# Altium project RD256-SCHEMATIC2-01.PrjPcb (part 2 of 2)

## Sheet 8.SchDoc
size 420 x 297 mm
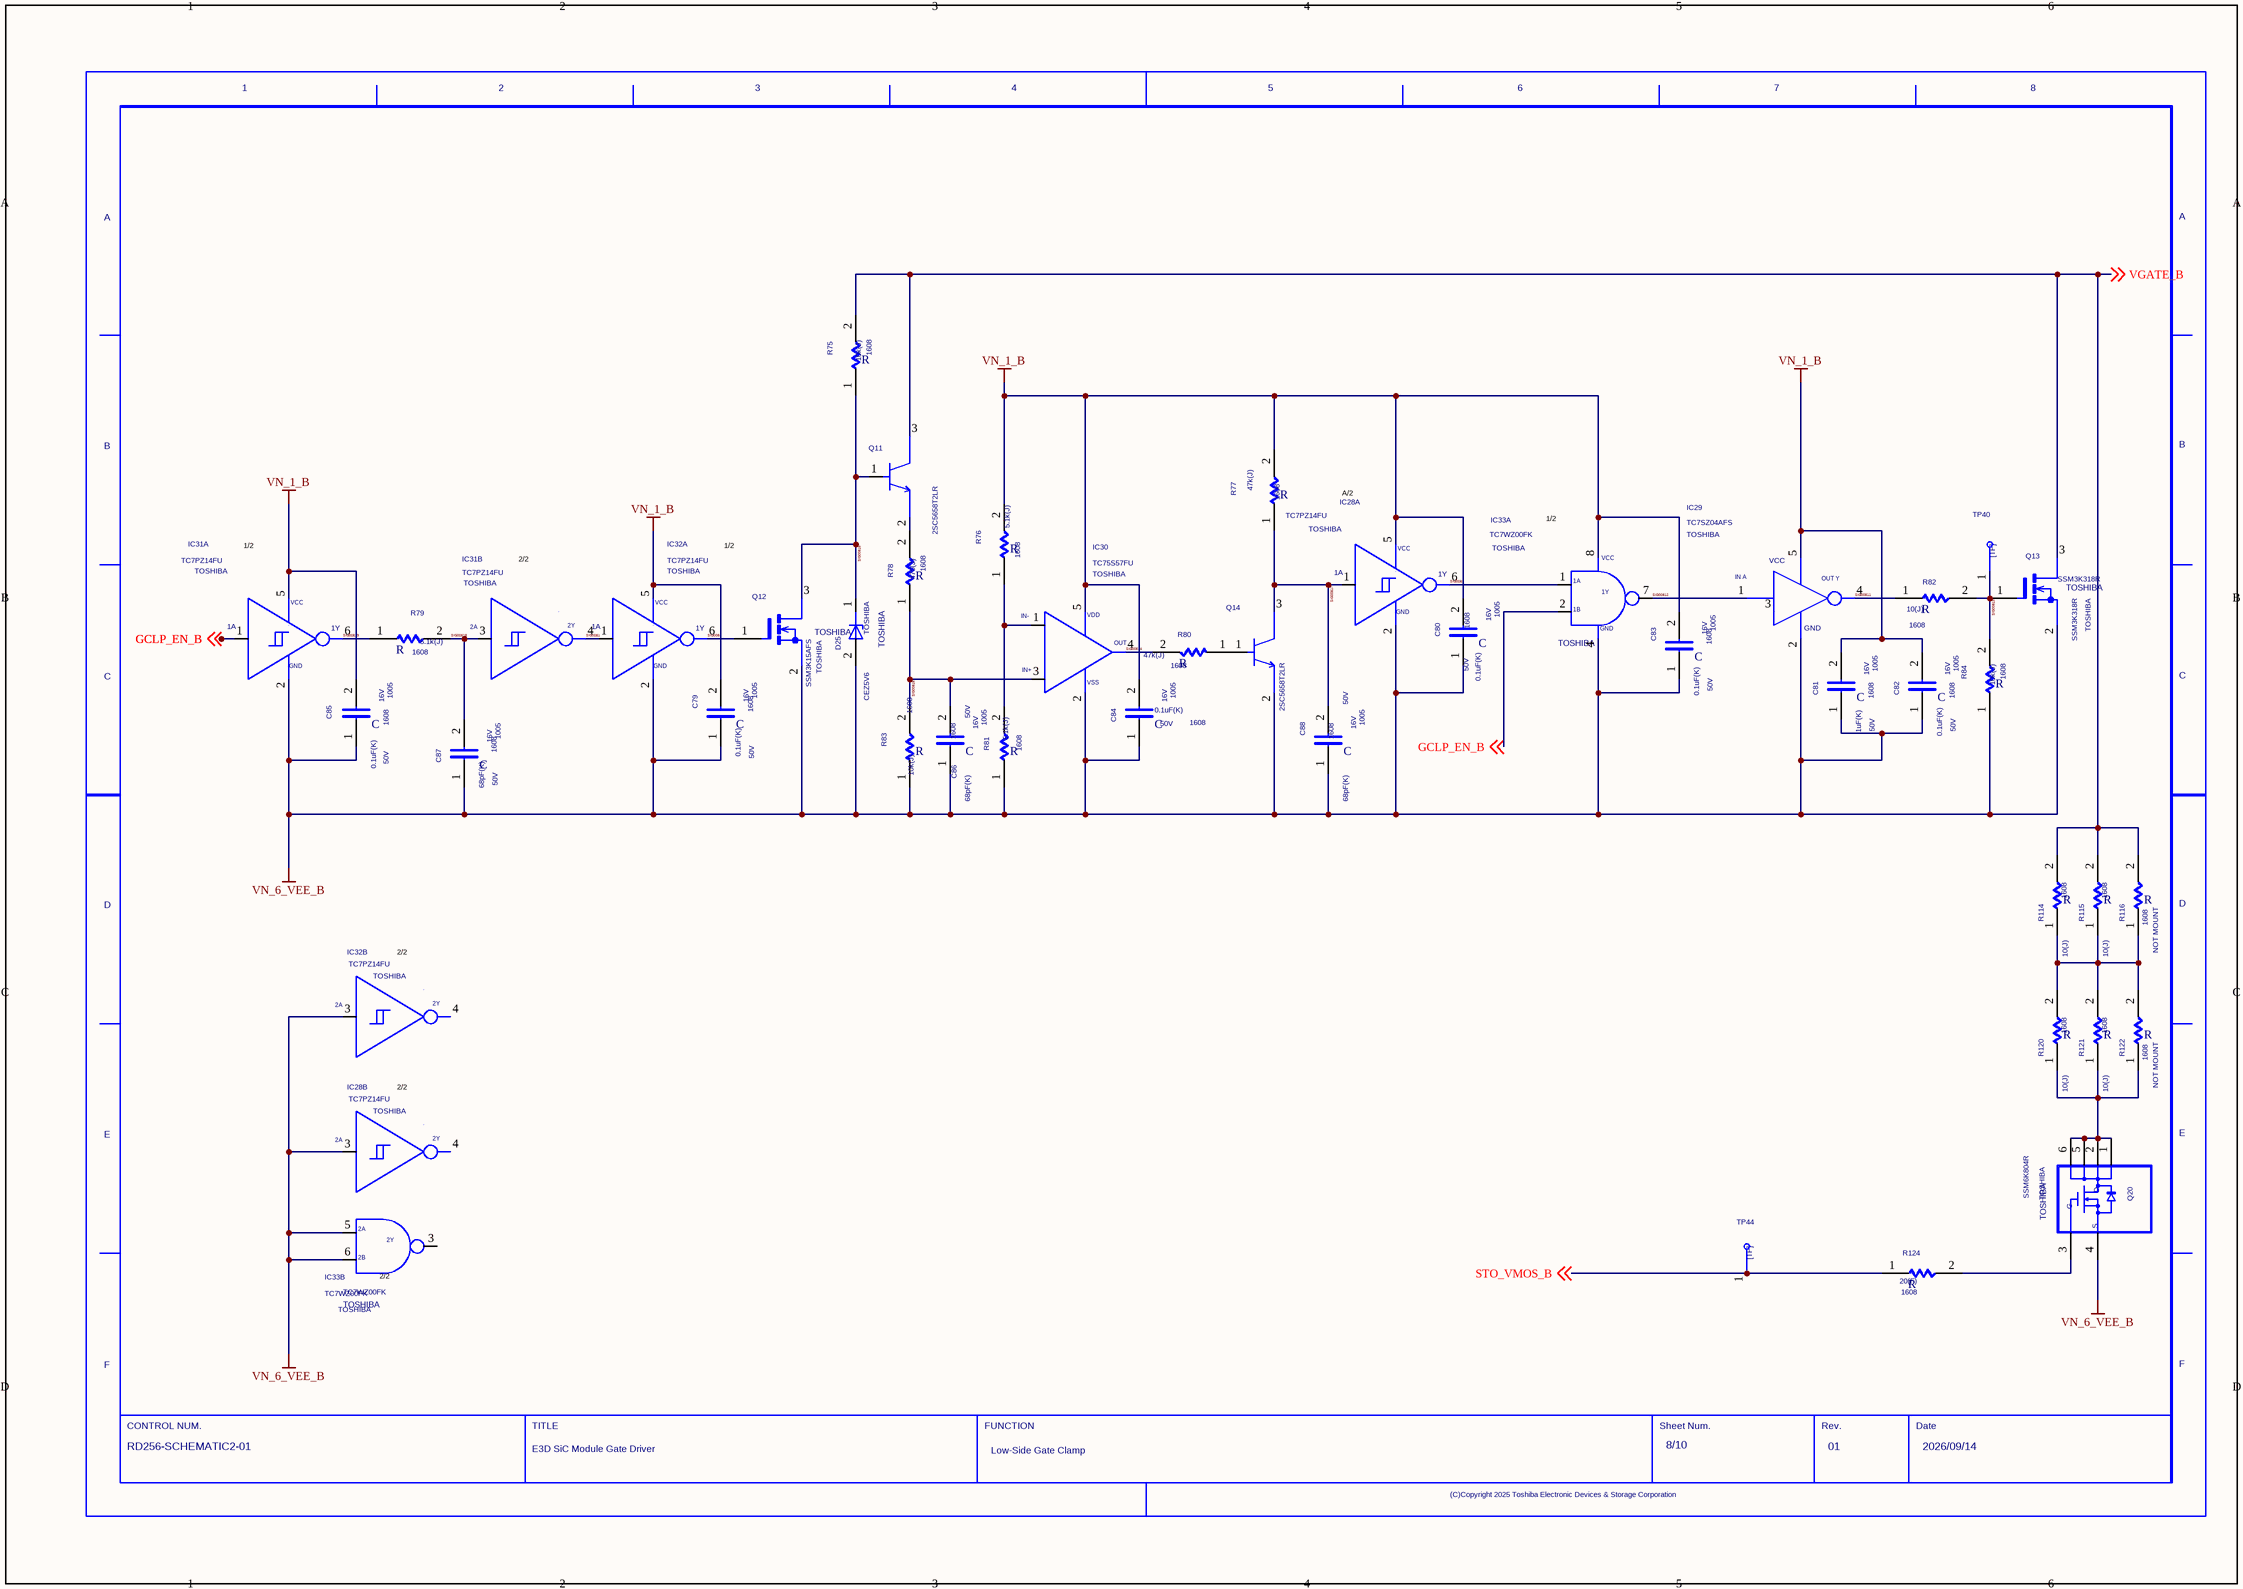
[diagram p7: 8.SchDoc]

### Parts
(Parts that share a designator on the sheet are numbered #1, #2 ... from top to bottom, then left to right.)
C79  VOLTAGE: 16V  CODE: 1005  VAL1: 0.1uF(K)  VAL2: 50V  SIZECODESMD: 1608  (hidden comment: C)
C80  VOLTAGE: 16V  CODE: 1005  VAL1: 0.1uF(K)  VAL2: 50V  SIZECODESMD: 1608  (hidden comment: C)
C81  VOLTAGE: 16V  CODE: 1005  VAL1: 1uF(K)  VAL2: 50V  SIZECODESMD: 1608  (hidden comment: C)
C82  VOLTAGE: 16V  CODE: 1005  VAL1: 0.1uF(K)  VAL2: 50V  SIZECODESMD: 1608  (hidden comment: C)
C83  VOLTAGE: 16V  CODE: 1005  VAL1: 0.1uF(K)  VAL2: 50V  SIZECODESMD: 1608  (hidden comment: C)
C84  VOLTAGE: 16V  CODE: 1005  VAL1: 0.1uF(K)  VAL2: 50V  SIZECODESMD: 1608  (hidden comment: C)
C85  VOLTAGE: 16V  CODE: 1005  VAL1: 0.1uF(K)  VAL2: 50V  SIZECODESMD: 1608  (hidden comment: C)
C86  VOLTAGE: 16V  CODE: 1005  VAL1: 68pF(K)  VAL2: 50V  SIZECODESMD: 1608  (hidden comment: C)
C87  VOLTAGE: 16V  CODE: 1005  VAL1: 68pF(K)  VAL2: 50V  SIZECODESMD: 1608  (hidden comment: C)
C88  VOLTAGE: 16V  CODE: 1005  VAL1: 68pF(K)  VAL2: 50V  SIZECODESMD: 1608  (hidden comment: C)
D25  VENDOR: TOSHIBA  (hidden comment: CEZ5V6)
IC28  VAL3: TC7PZ14FU  USERCOMPTEXT3: TOSHIBA  (hidden comment: TC7PZ17FU)  (parts A,B of 2)
IC29  USERCOMPTEXT3: TOSHIBA  (hidden comment: TC7SZ04AFS)
IC30  USERCOMPTEXT3: TOSHIBA  (hidden comment: TC75S57FU)
IC31  VAL3: TC7PZ14FU  USERCOMPTEXT3: TOSHIBA  (hidden comment: TC7PZ17FU)  (parts A,B of 2)
IC32  VAL3: TC7PZ14FU  USERCOMPTEXT3: TOSHIBA  (hidden comment: TC7PZ17FU)  (parts A,B of 2)
IC33  VENDOR: TOSHIBA  (hidden comment: TC7WZ00FK)  (parts A,B of 2)
Q11  VAL3: 2SC5658T2LR  (hidden comment: 2SC5658J)
Q12  VENDOR: TOSHIBA  (hidden comment: SSM3K15AFS)
Q13  VENDOR: TOSHIBA  (hidden comment: SSM3K318R)
Q14  VAL3: 2SC5658T2LR  (hidden comment: 2SC5658J)
Q20  VENDOR: TOSHIBA  (hidden comment: SSM6K804R)
R75  VAL1: 10k(J)  SIZECODESMD: 1608  (hidden comment: R)
R76  VAL1: 5.1k(J)  SIZECODESMD: 1608  (hidden comment: R)
R77  VAL1: 47k(J)  SIZECODESMD: 1608  (hidden comment: R)
R78  VAL1: 470(J)  SIZECODESMD: 1608  (hidden comment: R)
R79  VAL1: 5.1k(J)  SIZECODESMD: 1608  (hidden comment: R)
R80  VAL1: 47k(J)  SIZECODESMD: 1608  (hidden comment: R)
R81  VAL1: 5.1k(J)  SIZECODESMD: 1608  (hidden comment: R)
R82  VAL1: 10(J)  SIZECODESMD: 1608  (hidden comment: R)
R83  VAL1: 10k(J)  SIZECODESMD: 1608  (hidden comment: R)
R84  VAL1: 10k(J)  SIZECODESMD: 1608  (hidden comment: R)
R114  VAL1: 10(J)  SIZECODESMD: 1608  (hidden comment: R)
R115  VAL1: 10(J)  SIZECODESMD: 1608  (hidden comment: R)
R116  SIZECODESMD: 1608  NOTMOUNT: NOT MOUNT  (hidden comment: R)
R120  VAL1: 10(J)  SIZECODESMD: 1608  (hidden comment: R)
R121  VAL1: 10(J)  SIZECODESMD: 1608  (hidden comment: R)
R122  SIZECODESMD: 1608  NOTMOUNT: NOT MOUNT  (hidden comment: R)
R124  VAL1: 20(F)  SIZECODESMD: 1608  (hidden comment: R)
TP40  TP  (value not drawn)
TP44  TP  (value not drawn)
U?#8  REVISION: 01  SHEETNUMBER: 8/10  FUNCTION: Low-Side Gate Clamp  TITLE: E3D SiC Module Gate Driver  DRAWINGNUMBER: RD256-SCHEMATIC2-01  DATE: 2026/09/14  (hidden comment: WAKU_DEF100)

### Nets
VN_1_B: C79.2 C80.2 C81.2 C82.2 C83.2 C84.2 C85.2 IC28.5 IC29.5 IC30.5 IC31.5 IC32.5 IC33.8 R76.2 R77.2
VN_6_VEE_B: C79.1 C80.1 C81.1 C82.1 C83.1 C84.1 C85.1 C86.1 C87.1 C88.1 D25.2(A) IC28.2 IC28.3 IC29.2 IC30.2 IC31.2 IC32.2 IC32.3 IC33.4 IC33.5(2A) IC33.6(2B) Q12.2(S) Q13.2(S) Q14.2(E) Q20.4 R81.1 R83.1 R84.1
GCLP_EN_B: IC31.1 IC33.2 ; off-sheet GCLP_EN_B
SIG0081: IC31.4 IC32.1
SIG0082: Q20.3 R124.2
SIG0083: R114.1 R115.1 R116.1 R120.2 R121.2 R122.2
SIG0084: IC32.6 Q12.1(G)
SIG0085: IC28.6 IC33.1
SIG0086: IC30.1 R76.1 R81.2
SIG0089: Q11.2(E) R78.2
SIG00810: Q20.1 Q20.2 Q20.5 Q20.6 R120.1 R121.1 R122.1
SIG00811: IC29.4 R82.1
SIG00812: IC29.1 IC33.7
SIG00813: Q13.1(G) R82.2 R84.2 TP40.1
SIG00814: IC30.4 R80.2
SIG00815: C86.2 IC30.3 R78.1 R83.2
SIG00816: D25.1(C) Q11.1(B) Q12.3(D) R75.1
SIG00817: C88.2 IC28.1 Q14.3(C) R77.1
SIG00818: C87.2 IC31.3 R79.2
SIG00819: IC31.6 R79.1
STO_VMOS_B: R124.1 TP44.1 ; off-sheet STO_VMOS_B
VGATE_B: Q11.3(C) Q13.3(D) R75.2 R114.2 R115.2 R116.2 ; off-sheet VGATE_B
NetQ14_1: Q14.1(B) R80.1

Not connected (* = marked no-connect by the designer): IC28 4; IC29 3; IC32 4; IC33 3(2Y)

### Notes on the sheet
- A/2
- (near IC33) 1/2
- (near IC31) 1/2
- 2/2
- 1/2
- (near IC33) 2/2

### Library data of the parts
C79-C88 = C: ORIGINALSYMBOLORIGIN: (0,0); VC2: 0; PSPICETEMPLATE: C^@REFDES %1 %2 ?TOLERANCE¦C^@REFDES¦ @VALUE ?IC/IC=@IC/ TC=@TC1,@TC2 ?TOLERANCE¦\n.model C^@REFDES CAP C=1 DEV=@TOLERANCE% TC1=@TC1 TC2=@TC2 VC1=@VC1 VC2=@VC2¦; SAVECOUNT: 2; UPDATETIME: 08:48:12; UPDATEUSER: HP_Z8_KEYSHOT; INSTANCENAME: INS2265204
D25 = CEZ5V6: ORIGINALSYMBOLORIGIN: (0,0); PSPICETEMPLATE: X^@REFDES %C %A @MODEL; SAVEAREA0: -4630,-153,17114,13055; SAVECOUNT: 9; UPDATETIME: 08:16:22; UPDATEUSER: fukuda-y; TIME: 14:49:55; INSTANCENAME: INS2262356
IC28 IC31 IC32 = TC7PZ14FU_2: OriginalSymbolOrigin: (5080,15240); SWAP_INFO: (S1+S2); PSPICETEMPLATE: X^@REFDES %1A %GND %2A %2Y %VCC %1Y @MODEL; SPLIT_INST: TRUE; SAVECOUNT: 7; UPDATETIME: 19:09:34; UPDATEUSER: t5459927; TIME: 11:55:01; FUNCN: TC7PZ14FU_1; CaptureCellPackProp: TC7PZ14FU_2A
IC29 = TC7SZ04AFS: OriginalSymbolOrigin: (0,-5080); PSPICETEMPLATE: X^@REFDES %INA %GND %NC %OUTY %VCC @MODEL; SAVECOUNT: 6; UPDATETIME: 19:30:29; UPDATEUSER: t5459927; TIME: 11:55:02; INSTANCENAME: INS2262788
IC30 = TC75S57FU: OriginalSymbolOrigin: (2540,0); PSPICETEMPLATE: X^@REFDES %INN %VSS %INP %OUT %VDD @MODEL; SAVECOUNT: 3; UPDATETIME: 11:03:38; UPDATEUSER: t5459927; TIME: 08:48:15; INSTANCENAME: INS2262824
IC33 = TC7WZ00FK_2: PART NUMBER: TC7W00FK; ORIGINALSYMBOLORIGIN: (2540,-2540); DESCRIPTION-A: NAND 2ch Logic; PSPICETEMPLATE: X^@REFDES %1A %1B %2Y %GND %2A %2B %1Y %VCC @MODEL; ・: 7 V; SPLIT_INST: TRUE; ORDER: $pOrder; SWAP_INFO: (S1+S2); SAVECOUNT: 5; UPDATETIME: 16:09:46; UPDATEUSER: sptcae09; TIME: 08:52:39; FUNCN: TC7WZ00FK_1; CaptureCellPackProp: TC7WZ00FK_2A
Q11 = 2SC5658J: ORIGINALSYMBOLORIGIN: (0,0); PSPICETEMPLATE: X^@REFDES %C %B %E @MODEL; SAVEAREA0: -6194,-158,18648,15662; VENDOR: ROHM; SAVECOUNT: 8; UPDATETIME: 15:12:10; UPDATEUSER: 19910145; TIME: 09:39:04; INSTANCENAME: INS2262598
Q12 = SSM3K15AFS: PSPICETEMPLATE: X^@REFDES %D %G %S @MODEL; ORIGINALSYMBOLORIGIN: (0,0); SAVECOUNT: 2; UPDATETIME: 08:48:15; UPDATEUSER: HP_Z8_KEYSHOT; INSTANCENAME: INS2262996
Q13 = SSM3K318R: PSPICETEMPLATE: X^@REFDES %D %G %S @MODEL; ORIGINALSYMBOLORIGIN: (0,0); SAVECOUNT: 2; UPDATETIME: 08:48:16; UPDATEUSER: HP_Z8_KEYSHOT; INSTANCENAME: INS2261964
Q14 = 2SC5658J: ORIGINALSYMBOLORIGIN: (0,0); PSPICETEMPLATE: X^@REFDES %C %B %E @MODEL; SAVEAREA0: -6194,-158,18648,15662; VENDOR: ROHM; SAVECOUNT: 8; UPDATETIME: 15:12:10; UPDATEUSER: 19910145; TIME: 09:39:04; INSTANCENAME: INS2262860
Q20 = SSM6K804R: PSPICETEMPLATE: X^@REFDES %1 %2 %3 %4 %5 %6 @MODEL; ORIGINALSYMBOLORIGIN: (0,0); SAVEAREA0: -7120,-295,29516,23636; SAVECOUNT: 14; UPDATETIME: 08:48:15; UPDATEUSER: HP_Z8_KEYSHOT; INSTANCENAME: INS2262956
R75-R81 R83 R84 R114 R115 R120 R121 R124 = R: ORIGINALSYMBOLORIGIN: (0,0); PSPICETEMPLATE: R^@REFDES %1 %2 ?TOLERANCE¦R^@REFDES¦ @VALUE TC=@TC1,@TC2 ?TOLERANCE¦\n.model R^@REFDES RES R=1 DEV=@TOLERANCE% TC1=@TC1 TC2=@TC2¦; TC2: 0; VAL2: 100mW; SAVECOUNT: 2; UPDATETIME: 08:48:13; UPDATEUSER: HP_Z8_KEYSHOT; INSTANCENAME: INS2263832
R82 = R: ORIGINALSYMBOLORIGIN: (0,0); PSPICETEMPLATE: R^@REFDES %1 %2 ?TOLERANCE¦R^@REFDES¦ @VALUE TC=@TC1,@TC2 ?TOLERANCE¦\n.model R^@REFDES RES R=1 DEV=@TOLERANCE% TC1=@TC1 TC2=@TC2¦; TC2: 0; VAL2: 100mW; SAVECOUNT: 2; UPDATETIME: 08:48:13; UPDATEUSER: HP_Z8_KEYSHOT; INSTANCENAME: INS2262084
R116 R122 = R: ORIGINALSYMBOLORIGIN: (0,0); PSPICETEMPLATE: R^@REFDES %1 %2 ?TOLERANCE¦R^@REFDES¦ @VALUE TC=@TC1,@TC2 ?TOLERANCE¦\n.model R^@REFDES RES R=1 DEV=@TOLERANCE% TC1=@TC1 TC2=@TC2¦; TC2: 0; VAL2: 0.125; SAVECOUNT: 2; UPDATETIME: 08:48:13; UPDATEUSER: HP_Z8_KEYSHOT; INSTANCENAME: INS2263832
TP40 = TP: ORIGINALSYMBOLORIGIN: (0,0); SAVEAREA0: -242,-92,12810,7836; SAVECOUNT: 2; UPDATETIME: 16:18:11; UPDATEUSER: fukuda-y; TIME: 16:12:21; INSTANCENAME: INS2262622
TP44 = TP: ORIGINALSYMBOLORIGIN: (0,0); SAVEAREA0: -242,-92,12810,7836; SAVECOUNT: 2; UPDATETIME: 16:18:11; UPDATEUSER: fukuda-y; TIME: 16:12:21; INSTANCENAME: INS2262916
U?#8 = WAKU_DEF100: OriginalSymbolOrigin: (10160,284480); SAVECOUNT: 4; UPDATETIME: 12:22:01; UPDATEUSER: t5459927; TIME: 14:30:25; SAVEAREA0: -63393,-16950,474261,314592; PLOTTIME: HH:MM; SHTSAVECOUNT: 23

## Sheet 9.SchDoc
size 420 x 297 mm
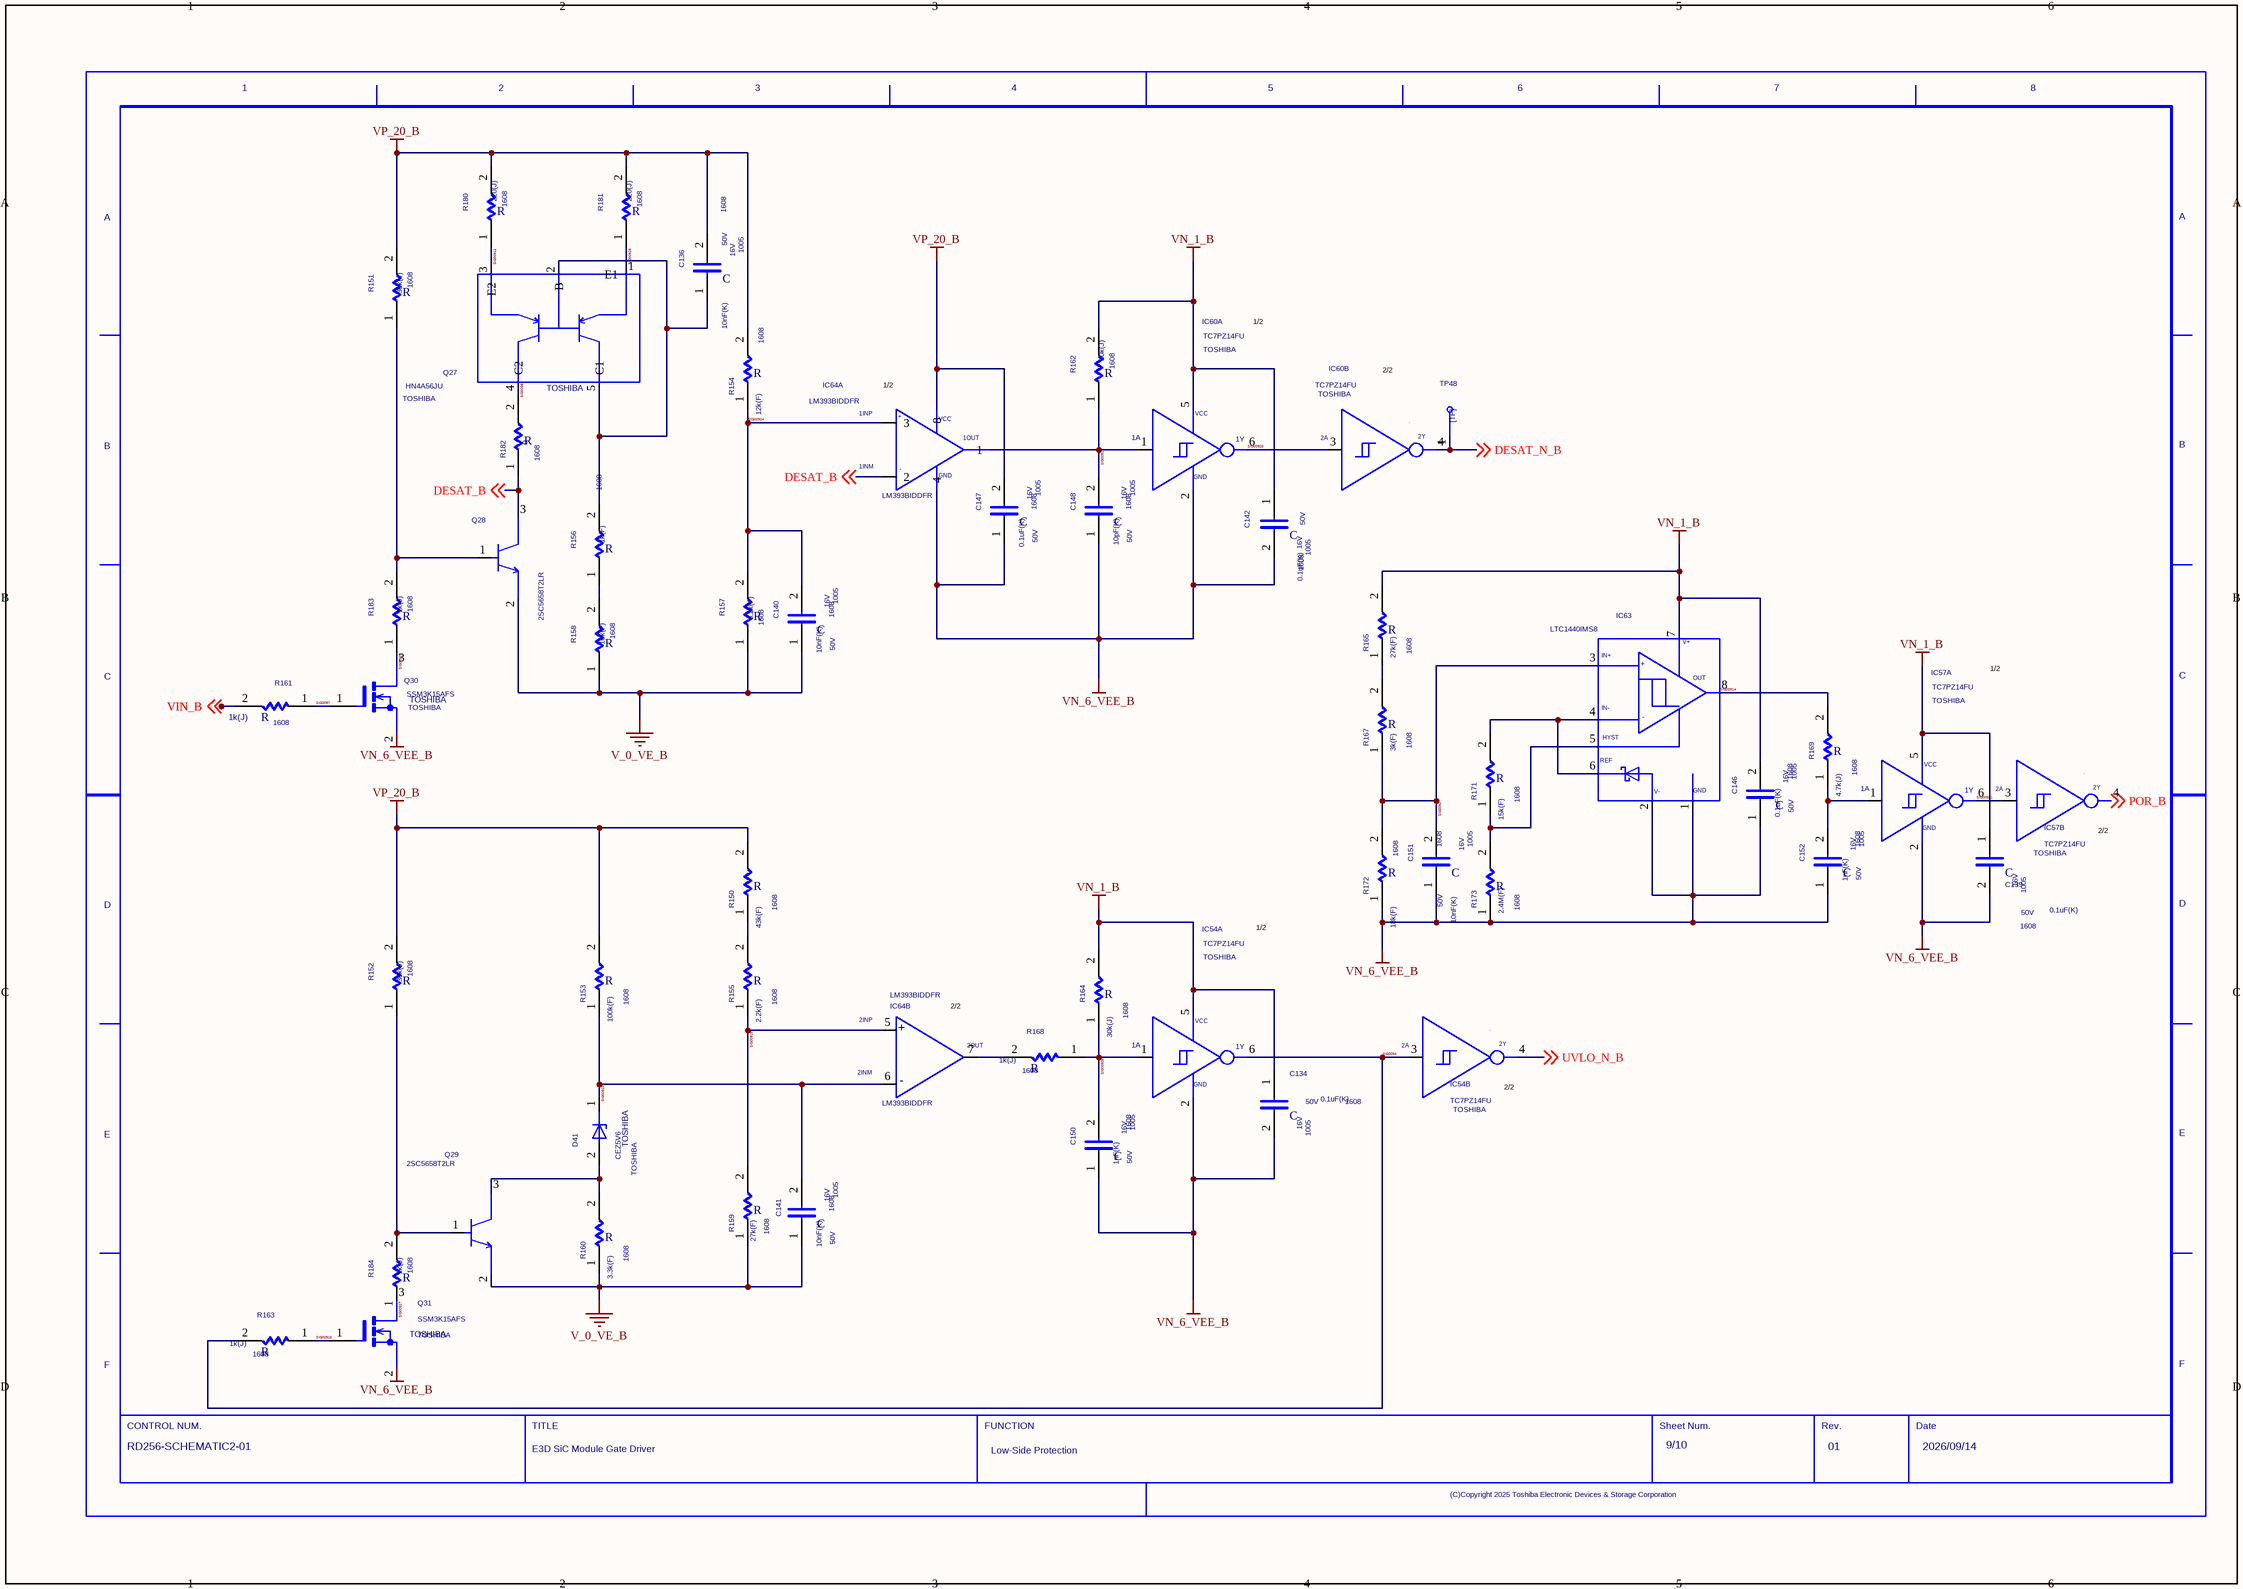
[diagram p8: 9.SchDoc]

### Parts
(Parts that share a designator on the sheet are numbered #1, #2 ... from top to bottom, then left to right.)
C134  VOLTAGE: 16V  CODE: 1005  VAL1: 0.1uF(K)  VAL2: 50V  SIZECODESMD: 1608  (hidden comment: C)
C136  VOLTAGE: 16V  CODE: 1005  VAL1: 10nF(K)  VAL2: 50V  SIZECODESMD: 1608  (hidden comment: C)
C139  VOLTAGE: 16V  CODE: 1005  VAL1: 0.1uF(K)  VAL2: 50V  SIZECODESMD: 1608  (hidden comment: C)
C140  VOLTAGE: 16V  CODE: 1005  VAL1: 10nF(K)  VAL2: 50V  SIZECODESMD: 1608  (hidden comment: C)
C141  VOLTAGE: 16V  CODE: 1005  VAL1: 10nF(K)  VAL2: 50V  SIZECODESMD: 1608  (hidden comment: C)
C142  VOLTAGE: 16V  CODE: 1005  VAL1: 0.1uF(K)  VAL2: 50V  SIZECODESMD: 1608  (hidden comment: C)
C146  VOLTAGE: 16V  CODE: 1005  VAL1: 0.1uF(K)  VAL2: 50V  SIZECODESMD: 1608  (hidden comment: C)
C147  VOLTAGE: 16V  CODE: 1005  VAL1: 0.1uF(K)  VAL2: 50V  SIZECODESMD: 1608  (hidden comment: C)
C148  VOLTAGE: 16V  CODE: 1005  VAL1: 10pF(K)  VAL2: 50V  SIZECODESMD: 1608  (hidden comment: C)
C150  VOLTAGE: 16V  CODE: 1005  VAL1: 1nF(K)  VAL2: 50V  SIZECODESMD: 1608  (hidden comment: C)
C151  VOLTAGE: 16V  CODE: 1005  VAL1: 10nF(K)  VAL2: 50V  SIZECODESMD: 1608  (hidden comment: C)
C152  VOLTAGE: 16V  CODE: 1005  VAL1: 1nF(K)  VAL2: 50V  SIZECODESMD: 1608  (hidden comment: C)
D41  VENDOR: TOSHIBA  (hidden comment: CEZ5V6)
IC54  VAL3: TC7PZ14FU  USERCOMPTEXT3: TOSHIBA  (hidden comment: TC7PZ17FU)  (parts A,B of 2)
IC57  VAL3: TC7PZ14FU  USERCOMPTEXT3: TOSHIBA  (hidden comment: TC7PZ17FU)  (parts A,B of 2)
IC60  VAL3: TC7PZ14FU  USERCOMPTEXT3: TOSHIBA  (hidden comment: TC7PZ17FU)  (parts A,B of 2)
IC63  VAL3: LTC1440IMS8  (hidden comment: LTC1440IS8)
IC64  VAL1: LM393BIDDFR  (hidden comment: LM393B_1)  (parts A,B of 2)
Q27  VENDOR: TOSHIBA  (hidden comment: HN4A56JU)
Q28  VAL3: 2SC5658T2LR  (hidden comment: 2SC5658J)
Q29  VAL3: 2SC5658T2LR  (hidden comment: 2SC5658J)
Q30  VENDOR: TOSHIBA  (hidden comment: SSM3K15AFS)
Q31  VENDOR: TOSHIBA  (hidden comment: SSM3K15AFS)
R150  VAL1: 43k(F)  SIZECODESMD: 1608  (hidden comment: R)
R151  VAL1: 30k(J)  SIZECODESMD: 1608  (hidden comment: R)
R152  VAL1: 30k(J)  SIZECODESMD: 1608  (hidden comment: R)
R153  VAL1: 100k(F)  SIZECODESMD: 1608  (hidden comment: R)
R154  VAL1: 12k(F)  SIZECODESMD: 1608  (hidden comment: R)
R155  VAL1: 2.2k(F)  SIZECODESMD: 1608  (hidden comment: R)
R156  VAL1: 1k(F)  SIZECODESMD: 1608  (hidden comment: R)
R157  VAL1: 8.2k(F)  SIZECODESMD: 1608  (hidden comment: R)
R158  VAL1: 10k(F)  SIZECODESMD: 1608  (hidden comment: R)
R159  VAL1: 27k(F)  SIZECODESMD: 1608  (hidden comment: R)
R160  VAL1: 3.3k(F)  SIZECODESMD: 1608  (hidden comment: R)
R161  VAL1: 1k(J)  SIZECODESMD: 1608  (hidden comment: R)
R162  VAL1: 30k(J)  SIZECODESMD: 1608  (hidden comment: R)
R163  VAL1: 1k(J)  SIZECODESMD: 1608  (hidden comment: R)
R164  VAL1: 30k(J)  SIZECODESMD: 1608  (hidden comment: R)
R165  VAL1: 27k(F)  SIZECODESMD: 1608  (hidden comment: R)
R167  VAL1: 3k(F)  SIZECODESMD: 1608  (hidden comment: R)
R168  VAL1: 1k(J)  SIZECODESMD: 1608  (hidden comment: R)
R169  VAL1: 4.7k(J)  SIZECODESMD: 1608  (hidden comment: R)
R171  VAL1: 15k(F)  SIZECODESMD: 1608  (hidden comment: R)
R172  VAL1: 18k(F)  SIZECODESMD: 1608  (hidden comment: R)
R173  VAL1: 2.4M(F)  SIZECODESMD: 1608  (hidden comment: R)
R180  VAL1: 220(J)  SIZECODESMD: 1608  (hidden comment: R)
R181  VAL1: 220(J)  SIZECODESMD: 1608  (hidden comment: R)
R182  VAL1: 0  SIZECODESMD: 1608  (hidden comment: R)
R183  VAL1: 1k(J)  SIZECODESMD: 1608  (hidden comment: R)
R184  VAL1: 1k(J)  SIZECODESMD: 1608  (hidden comment: R)
TP48  TP  (value not drawn)
U?#9  REVISION: 01  SHEETNUMBER: 9/10  FUNCTION: Low-Side Protection  TITLE: E3D SiC Module Gate Driver  DRAWINGNUMBER: RD256-SCHEMATIC2-01  DATE: 2026/09/14  (hidden comment: WAKU_DEF100)

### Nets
V_0_VE_B: C140.1 C141.1 Q28.2(E) Q29.2(E) R157.1 R158.1 R159.1 R160.1
VN_1_B: C134.1 C139.1 C142.1 C146.2 IC54.5 IC57.5 IC60.5 IC63.7(V+) R162.2 R164.2 R165.2
VN_6_VEE_B: C134.2 C139.2 C142.2 C146.1 C147.1 C148.1 C150.1 C151.1 C152.1 IC54.2 IC57.2 IC60.2 IC63.1(GND) IC63.2(V-) IC64.4 Q30.2(S) Q31.2(S) R172.1 R173.1
VP_20_B: C136.2 C147.2 IC64.8 R150.2 R151.2 R152.2 R153.2 R154.2 R180.2 R181.2
DESAT_B: IC64.2 Q28.3(C) R182.1 ; off-sheet DESAT_B
DESAT_N_B: IC60.4 TP48.1 ; off-sheet DESAT_N_B
POR_B: IC57.4 ; off-sheet POR_B
SIG0091: C148.2 IC60.1 IC64.1 R162.1
SIG0092: C151.2 IC63.3(IN+) R167.1 R172.2
SIG0093: Q29.1(B) R152.1 R184.2
SIG0094: IC54.3 IC54.6 R163.2
SIG0095: IC64.7 R168.2
SIG0096: Q27.4(C2) R182.2
SIG0097: Q30.1(G) R161.1
SIG0098: IC63.4(IN-) IC63.6(REF) R171.2
SIG0099: R165.1 R167.2
SIG00910: Q28.1(B) R151.1 R183.2
SIG00911: Q27.3(E2) R180.1
SIG00912: IC63.5(HYST) R171.1 R173.2
SIG00913: D41.2(A) Q29.3(C) R160.2
SIG00914: IC63.8(OUT) R169.2
SIG00915: Q31.1(G) R163.1
SIG00916: R156.1 R158.2
SIG00917: C136.1 Q27.2(B) Q27.5(C1) R156.2
SIG00918: R150.1 R155.2
SIG00919: IC64.5 R155.1 R159.2
SIG00920: C152.2 IC57.1 R169.1
SIG00921: IC57.3 IC57.6
SIG00922: Q30.3(D) R183.1
SIG00923: C141.2 D41.1(C) IC64.6 R153.1
SIG00924: C140.2 IC64.3 R154.1 R157.2
SIG00925: IC60.3 IC60.6
SIG00926: C150.2 IC54.1 R164.1 R168.1
SIG00927: Q31.3(D) R184.1
SIG00928: Q27.1(E1) R181.1
UVLO_N_B: IC54.4 ; off-sheet UVLO_N_B
VIN_B: R161.2 ; off-sheet VIN_B

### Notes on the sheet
- 1/2
- (near IC64) 1/2
- 2/2
- (near IC57) 2/2
- (near IC64) 2/2
- (near IC54) 2/2

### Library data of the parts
C134 C136 C139-C142 C146-C148 C150-C152 = C: as C79-C88 on sheet 8
D41 = CEZ5V6: ORIGINALSYMBOLORIGIN: (0,0); PSPICETEMPLATE: X^@REFDES %C %A @MODEL; SAVEAREA0: -4630,-153,17114,13055; SAVECOUNT: 9; UPDATETIME: 08:16:22; UPDATEUSER: fukuda-y; TIME: 14:49:55; INSTANCENAME: INS2265024
IC54 IC57 IC60 = TC7PZ14FU_2: OriginalSymbolOrigin: (5080,15240); SWAP_INFO: (S1+S2); PSPICETEMPLATE: X^@REFDES %1A %GND %2A %2Y %VCC %1Y @MODEL; SPLIT_INST: TRUE; SAVECOUNT: 7; UPDATETIME: 19:09:34; UPDATEUSER: t5459927; TIME: 11:55:01; INSTANCENAME: INS2254016; FUNCN: TC7PZ14FU_1; CaptureCellPackProp: TC7PZ14FU_2A
IC63 = LTC1440IS8: OriginalSymbolOrigin: (0,0); PSPICETEMPLATE: X^@REFDES %GND %V- %IN+ %IN- %HYST %REF %V+ %OUT @MODEL; SAVECOUNT: 4; UPDATETIME: 17:22:21; UPDATEUSER: t5459927; TIME: 08:48:16; INSTANCENAME: INS2264292
IC64 = LM393B_1: OriginalSymbolOrigin: (2540,0); SWAP_INFO: (S1+S2); VENDOR: TI; COMP: LM393B; PSPICETEMPLATE: X^@REFDES %INN %VSS %INP %OUT %VDD @MODEL; SPLIT_INST: TRUE; SAVECOUNT: 5; UPDATETIME: 19:15:42; UPDATEUSER: t5459927; TIME: 08:48:12; INSTANCENAME: INS2264892; CaptureCellPackProp: LM393B_1A
Q27 = HN4A56JU: OriginalSymbolOrigin: (0,0); PSPICETEMPLATE: X^@REFDES %B1 %E %B2 %C2 %C1 @MODEL; SAVECOUNT: 2; UPDATETIME: 08:48:13; UPDATEUSER: HP_Z8_KEYSHOT; INSTANCENAME: INS2265108
Q28 = 2SC5658J: ORIGINALSYMBOLORIGIN: (0,0); PSPICETEMPLATE: X^@REFDES %C %B %E @MODEL; SAVEAREA0: -6194,-158,18648,15662; VENDOR: ROHM; SAVECOUNT: 8; UPDATETIME: 15:12:10; UPDATEUSER: 19910145; TIME: 09:39:04; INSTANCENAME: INS2264212
Q29 = 2SC5658J: ORIGINALSYMBOLORIGIN: (0,0); PSPICETEMPLATE: X^@REFDES %C %B %E @MODEL; SAVEAREA0: -6194,-158,18648,15662; VENDOR: ROHM; SAVECOUNT: 8; UPDATETIME: 15:12:10; UPDATEUSER: 19910145; TIME: 09:39:04; INSTANCENAME: INS2264508
Q30 = SSM3K15AFS: PSPICETEMPLATE: X^@REFDES %D %G %S @MODEL; ORIGINALSYMBOLORIGIN: (0,0); SAVECOUNT: 2; UPDATETIME: 08:48:15; UPDATEUSER: HP_Z8_KEYSHOT; INSTANCENAME: INS2265300
Q31 = SSM3K15AFS: PSPICETEMPLATE: X^@REFDES %D %G %S @MODEL; ORIGINALSYMBOLORIGIN: (0,0); SAVECOUNT: 2; UPDATETIME: 08:48:15; UPDATEUSER: HP_Z8_KEYSHOT; INSTANCENAME: INS2264184
R150-R165 R167-R169 R171-R173 R180 R181 R183 R184 = R: as R75-R81 on sheet 8
R182 = R: ORIGINALSYMBOLORIGIN: (0,0); PSPICETEMPLATE: R^@REFDES %1 %2 ?TOLERANCE¦R^@REFDES¦ @VALUE TC=@TC1,@TC2 ?TOLERANCE¦\n.model R^@REFDES RES R=1 DEV=@TOLERANCE% TC1=@TC1 TC2=@TC2¦; VAL2: 0.125; SAVECOUNT: 2; UPDATETIME: 08:48:13; UPDATEUSER: HP_Z8_KEYSHOT; INSTANCENAME: INS2264424
TP48 = TP: ORIGINALSYMBOLORIGIN: (0,0); SAVEAREA0: -242,-92,12810,7836; SAVECOUNT: 2; UPDATETIME: 16:18:11; UPDATEUSER: fukuda-y; TIME: 16:12:21; INSTANCENAME: INS2264820
U?#9 = WAKU_DEF100: OriginalSymbolOrigin: (10160,284480); SAVECOUNT: 4; UPDATETIME: 12:22:00; UPDATEUSER: t5459927; TIME: 14:30:25; SAVEAREA0: -63393,-16950,474261,314592; PLOTTIME: HH:MM; SHTSAVECOUNT: 24

## Sheet 10.SchDoc
size 420 x 297 mm
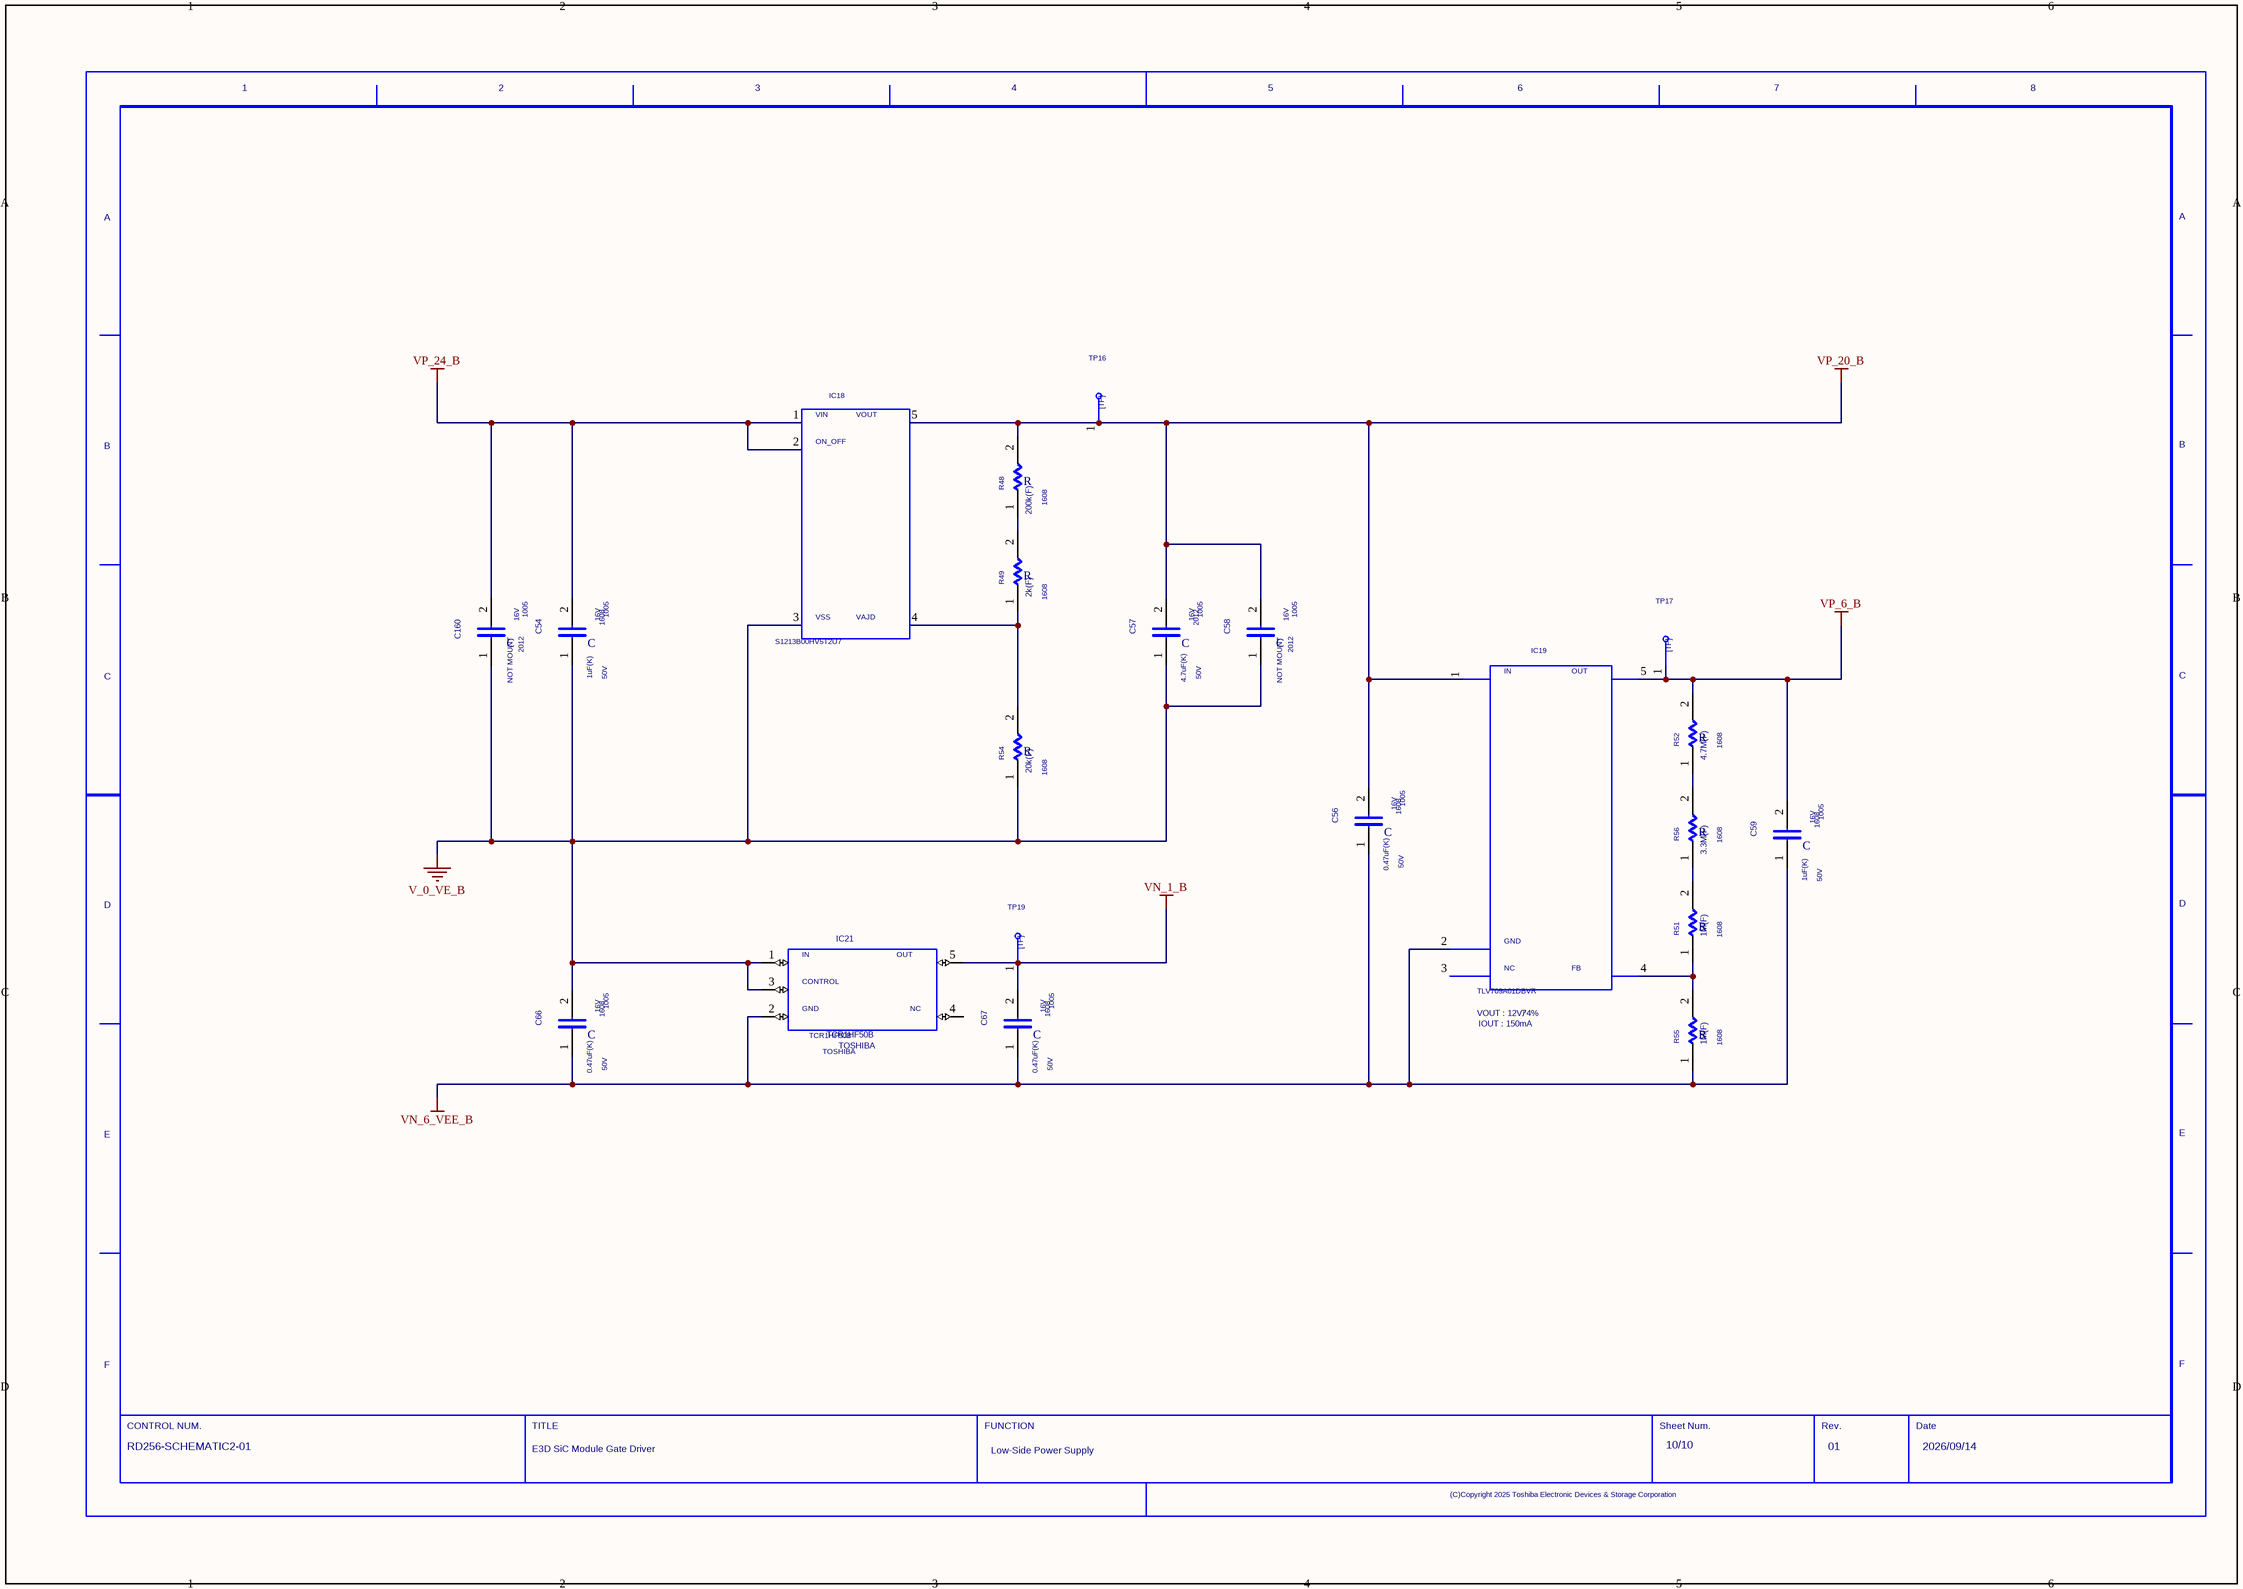
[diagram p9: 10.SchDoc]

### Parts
(Parts that share a designator on the sheet are numbered #1, #2 ... from top to bottom, then left to right.)
C54  VOLTAGE: 16V  CODE: 1005  VAL1: 1uF(K)  VAL2: 50V  SIZECODESMD: 1608  (hidden comment: C)
C56  VOLTAGE: 16V  CODE: 1005  VAL1: 0.47uF(K)  VAL2: 50V  SIZECODESMD: 1608  (hidden comment: C)
C57  VOLTAGE: 16V  CODE: 1005  VAL1: 4.7uF(K)  VAL2: 50V  SIZECODESMD: 2012  (hidden comment: C)
C58  VOLTAGE: 16V  CODE: 1005  SIZECODESMD: 2012  NOTMOUNT: NOT MOUNT  (hidden comment: C)
C59  VOLTAGE: 16V  CODE: 1005  VAL1: 1uF(K)  VAL2: 50V  SIZECODESMD: 1608  (hidden comment: C)
C66  VOLTAGE: 16V  CODE: 1005  VAL1: 0.47uF(K)  VAL2: 50V  SIZECODESMD: 1608  (hidden comment: C)
C67  VOLTAGE: 16V  CODE: 1005  VAL1: 0.47uF(K)  VAL2: 50V  SIZECODESMD: 1608  (hidden comment: C)
C160  VOLTAGE: 16V  CODE: 1005  SIZECODESMD: 2012  NOTMOUNT: NOT MOUNT  (hidden comment: C)
IC18  S1213B00HV5T2U7
IC19  CLASS: IOUT : 150mA  NC: VOUT : 12Vｱ4%  VAL3: TLV709A01DBVR  (hidden comment: TLV709)
IC21  TCR1HF50B  VENDOR: TOSHIBA
R48  VAL1: 200k(F)  SIZECODESMD: 1608  (hidden comment: R)
R49  VAL1: 2k(F)  SIZECODESMD: 1608  (hidden comment: R)
R51  VAL1: 1M(F)  SIZECODESMD: 1608  (hidden comment: R)
R52  VAL1: 4.7M(F)  SIZECODESMD: 1608  (hidden comment: R)
R54  VAL1: 20k(F)  SIZECODESMD: 1608  (hidden comment: R)
R55  VAL1: 1M(F)  SIZECODESMD: 1608  (hidden comment: R)
R56  VAL1: 3.3M(F)  SIZECODESMD: 1608  (hidden comment: R)
TP16  TP  (value not drawn)
TP17  TP  (value not drawn)
TP19  TP  (value not drawn)
U?#10  REVISION: 01  SHEETNUMBER: 10/10  FUNCTION: Low-Side Power Supply  TITLE: E3D SiC Module Gate Driver  DRAWINGNUMBER: RD256-SCHEMATIC2-01  DATE: 2026/09/14  (hidden comment: WAKU_DEF100)

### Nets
V_0_VE_B: C54.1 C57.1 C58.1 C66.2 C160.1 IC18.3 IC21.1 IC21.3 R54.1
VN_1_B: C67.2 IC21.5 TP19.1
VN_6_VEE_B: C56.1 C59.1 C66.1 C67.1 IC19.2 IC21.2 R55.1
VP_6_B: C59.2 IC19.5 R52.2 TP17.1
VP_20_B: C56.2 C57.2 C58.2 IC18.5 IC19.1 R48.2 TP16.1
VP_24_B: C54.2 C160.2 IC18.1 IC18.2
SIG0101: IC18.4 R49.1 R54.2
SIG0102: R52.1 R56.2
SIG0103: IC19.4 R51.1 R55.2
SIG0104: R48.1 R49.2
SIG0105: R51.2 R56.1

Not connected (* = marked no-connect by the designer): IC19 3; IC21 4

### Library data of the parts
C54 C56-C59 C66 C67 C160 = C: ORIGINALSYMBOLORIGIN: (0,0); VC2: 0; PSPICETEMPLATE: C^@REFDES %1 %2 ?TOLERANCE¦C^@REFDES¦ @VALUE ?IC/IC=@IC/ TC=@TC1,@TC2 ?TOLERANCE¦\n.model C^@REFDES CAP C=1 DEV=@TOLERANCE% TC1=@TC1 TC2=@TC2 VC1=@VC1 VC2=@VC2¦; SAVECOUNT: 2; UPDATETIME: 08:48:12; UPDATEUSER: HP_Z8_KEYSHOT; INSTANCENAME: INS2266227
IC18 = S1213B00HV5T2U7: OriginalSymbolOrigin: (0,0); PSPICETEMPLATE: X^@REFDES %ADJUST %OUTPUT %INPUT @MODEL; SAVECOUNT: 7; UPDATETIME: 09:48:38; UPDATEUSER: t5459927; TIME: 08:48:13; INSTANCENAME: INS2266489
IC19 = TLV709: OriginalSymbolOrigin: (0,0); PSPICETEMPLATE: X^@REFDES %IN %GND %NC %FB %OUT @MODEL; SAVECOUNT: 5; UPDATETIME: 10:01:49; UPDATEUSER: t5459927; TIME: 08:48:16; INSTANCENAME: INS2266385
IC21 = TCR1HF50B: OriginalSymbolOrigin: (-2540,0); PSPICETEMPLATE: X^@REFDES %IN %GND %CONTROL %NC %OUT @MODEL; SAVECOUNT: 4; UPDATETIME: 10:27:35; UPDATEUSER: t5459927; TIME: 11:54:59; INSTANCENAME: INS2266087
R48 R49 R51 R52 R54-R56 = R: ORIGINALSYMBOLORIGIN: (0,0); PSPICETEMPLATE: R^@REFDES %1 %2 ?TOLERANCE¦R^@REFDES¦ @VALUE TC=@TC1,@TC2 ?TOLERANCE¦\n.model R^@REFDES RES R=1 DEV=@TOLERANCE% TC1=@TC1 TC2=@TC2¦; TC2: 0; VAL2: 100mW; SAVECOUNT: 2; UPDATETIME: 08:48:13; UPDATEUSER: HP_Z8_KEYSHOT; INSTANCENAME: INS2266059
TP16 = TP: ORIGINALSYMBOLORIGIN: (0,0); SAVEAREA0: -242,-92,12810,7836; SAVECOUNT: 2; UPDATETIME: 16:18:11; UPDATEUSER: fukuda-y; TIME: 16:12:21; INSTANCENAME: INS2266317
TP17 = TP: ORIGINALSYMBOLORIGIN: (0,0); SAVEAREA0: -242,-92,12810,7836; SAVECOUNT: 2; UPDATETIME: 16:18:11; UPDATEUSER: fukuda-y; TIME: 16:12:21; INSTANCENAME: INS2266305
TP19 = TP: ORIGINALSYMBOLORIGIN: (0,0); SAVEAREA0: -242,-92,12810,7836; SAVECOUNT: 2; UPDATETIME: 16:18:11; UPDATEUSER: fukuda-y; TIME: 16:12:21; INSTANCENAME: INS2266293
U?#10 = WAKU_DEF100: OriginalSymbolOrigin: (10160,284480); SAVECOUNT: 4; UPDATETIME: 11:30:54; UPDATEUSER: t5459927; TIME: 14:30:25; SAVEAREA0: -63393,-16950,474261,314592; PLOTTIME: HH:MM; SHTSAVECOUNT: 18

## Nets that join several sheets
V_0_VE_A: 1 (CN2.3 CN2.4), 2 (13 pins), 4 (8 pins), 5 (9 pins), 7 (D35.2)
V_0_VE_B: 6 (CN3.3 CN3.4), 7 (13 pins), 9 (8 pins), 10 (9 pins)
VN_1_A: 1 (15 pins), 2 (6 pins), 3 (15 pins), 4 (11 pins), 5 (C48.2 IC17.5 TP14.1)
VN_1_B: 6 (15 pins), 7 (6 pins), 8 (15 pins), 9 (11 pins), 10 (C67.2 IC21.5 TP19.1)
VN_6_VEE_A: 1 (17 pins), 2 (15 pins), 3 (28 pins), 4 (19 pins), 5 (7 pins)
VN_6_VEE_B: 6 (17 pins), 7 (15 pins), 8 (28 pins), 9 (19 pins), 10 (7 pins)
VP_6_A: 2 (C95.2 IC35.1), 5 (C40.2 IC15.5 R31.2 TP12.1)
VP_6_B: 7 (C107.2 IC39.1), 10 (C59.2 IC19.5 R52.2 TP17.1)
VP_20_A: 2 (9 pins), 4 (10 pins), 5 (7 pins)
VP_20_B: 7 (9 pins), 9 (10 pins), 10 (7 pins)
VP_24_A: 1 (CN2.1 CN2.2), 5 (C35.2 C159.2 IC14.1 IC14.2)
VP_24_B: 6 (CN3.1 CN3.2), 10 (C54.2 C160.2 IC18.1 IC18.2)
DESAT_A: 2 (6 pins), 4 (IC51.2 Q22.3 R177.1)
DESAT_B: 7 (6 pins), 9 (IC64.2 Q28.3 R182.1)
DESAT_N_A: 1 (IC49.5), 4 (IC48.4 TP46.1)
DESAT_N_B: 6 (IC61.5), 9 (IC60.4 TP48.1)
GCLP_EN_A: 1 (IC46.3), 3 (IC25.1 IC27.2)
GCLP_EN_B: 6 (IC58.3), 8 (IC31.1 IC33.2)
POR_A: 1 (IC46.2 IC49.1), 4 (IC45.4)
POR_B: 6 (IC58.2 IC61.1), 9 (IC57.4)
PRED_EN_A: 1 (5 pins), 2 (C155.1 IC35.6)
PRED_EN_B: 6 (5 pins), 7 (C158.1 IC39.6)
STO_VMOS_A: 1 (IC44.6), 3 (R104.1 TP43.1)
STO_VMOS_B: 6 (IC56.6), 8 (R124.1 TP44.1)
UVLO_N_A: 1 (IC46.1), 4 (IC43.4)
UVLO_N_B: 6 (IC58.1), 9 (IC54.4)
VGATE_A: 2 (13 pins), 3 (6 pins)
VGATE_B: 7 (13 pins), 8 (6 pins)
VIN_A: 1 (IC44.3 IC47.7), 2 (IC36.1), 4 (R136.2)
VIN_B: 6 (IC56.3 IC59.7), 7 (IC40.1), 9 (R161.2)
